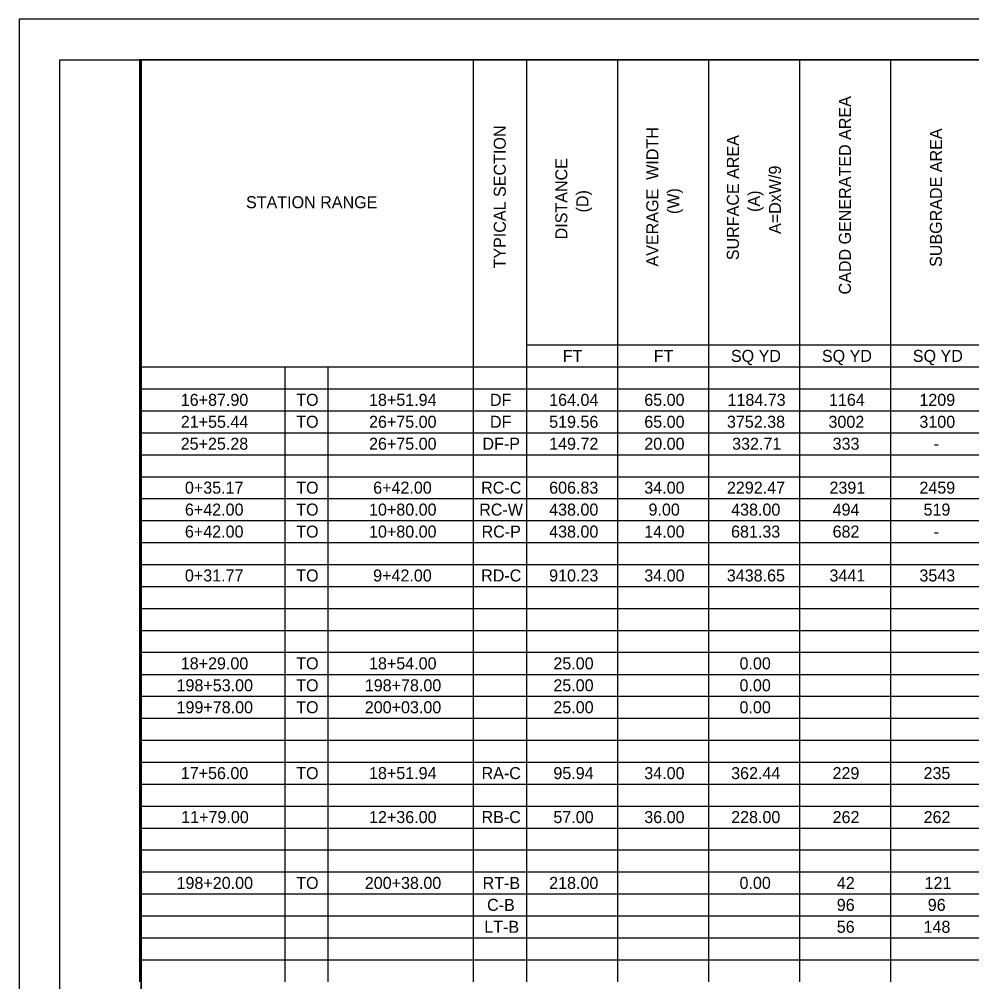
# Model space of a CAD drawing. Extents: x 0 to 34, y 0 to 22.
# Drawn here: x 0 to 11.72, y 10.15 to 22 of the extents above; entities that cross this region are included whole.
import ezdxf

# ---------------------------------------------------------------- set-up
doc = ezdxf.new("R2010")
doc.units = 0
for name, color, linetype in [('SH_Border', 7, 'Continuous'), ('SH_Cut_Line', 7, 'Continuous'), ('SH_Text', 7, 'Continuous')]:
    doc.layers.add(name, color=color, linetype=linetype)

msp = doc.modelspace()

# ---------------------------------------------------------------- linework, layer by layer
at = {"layer": 'SH_Border'}
for points in [[(0.5, 21.5), (1.5, 21.5), (1.5, 0.5), (0.5, 0.5)], [(1.5, 21.5), (33.5, 21.5), (33.5, 0.5), (1.5, 0.5)]]:
    msp.add_lwpolyline(points, close=True, dxfattribs=at)
at = {"layer": 'SH_Cut_Line'}
msp.add_lwpolyline([(0, 0), (34, 0), (34, 22), (0, 22)], close=True, dxfattribs=at)
at = {"layer": 'SH_Text'}
for p, q in [((1.479, 21.505), (6.242, 21.505)), ((1.479, 21.505), (1.479, 21.235)), ((5.585, 21.505), (5.585, 21.235)), ((6.242, 21.505), (7.362, 21.505)), ((6.242, 21.505), (6.242, 21.235)), ((7.362, 21.505), (8.482, 21.505)), ((7.362, 21.505), (7.362, 21.235)), ((8.482, 21.505), (10.722, 21.505)), ((8.482, 21.505), (8.482, 21.235)), ((9.602, 21.505), (9.602, 21.235)), ((10.722, 21.505), (11.841, 21.505)), ((10.722, 21.505), (10.722, 21.235)), ((1.479, 21.235), (1.479, 20.965)), ((5.585, 21.235), (5.585, 20.965)), ((6.242, 21.235), (6.242, 20.965)), ((7.362, 21.235), (7.362, 20.965)), ((8.482, 21.235), (8.482, 20.965)), ((9.602, 21.235), (9.602, 20.965)), ((10.722, 21.235), (10.722, 20.965)), ((1.479, 20.965), (1.479, 20.694)), ((5.585, 20.965), (5.585, 20.694)), ((6.242, 20.965), (6.242, 20.694)), ((7.362, 20.965), (7.362, 20.694)), ((8.482, 20.965), (8.482, 20.694)), ((9.602, 20.965), (9.602, 20.694)), ((10.722, 20.965), (10.722, 20.694)), ((1.479, 20.694), (1.479, 20.154)), ((5.585, 20.694), (5.585, 20.154)), ((6.242, 20.694), (6.242, 20.154)), ((7.362, 20.694), (7.362, 20.154)), ((8.482, 20.694), (8.482, 20.154)), ((9.602, 20.694), (9.602, 20.154)), ((10.722, 20.694), (10.722, 20.154)), ((1.479, 20.154), (1.479, 19.883)), ((5.585, 20.154), (5.585, 19.883)), ((6.242, 20.154), (6.242, 19.883)), ((7.362, 20.154), (7.362, 19.883)), ((8.482, 20.154), (8.482, 19.883)), ((9.602, 20.154), (9.602, 19.883)), ((10.722, 20.154), (10.722, 19.883)), ((1.479, 19.883), (1.479, 19.613)), ((5.585, 19.883), (5.585, 19.613)), ((6.242, 19.883), (6.242, 19.613)), ((7.362, 19.883), (7.362, 19.613)), ((8.482, 19.883), (8.482, 19.613)), ((9.602, 19.883), (9.602, 19.613)), ((10.722, 19.883), (10.722, 19.613)), ((1.479, 19.613), (1.479, 19.343)), ((5.585, 19.613), (5.585, 19.343)), ((6.242, 19.613), (6.242, 19.343)), ((7.362, 19.613), (7.362, 19.343)), ((8.482, 19.613), (8.482, 19.343)), ((9.602, 19.613), (9.602, 19.343)), ((10.722, 19.613), (10.722, 19.343)), ((1.479, 19.343), (1.479, 19.072)), ((5.585, 19.343), (5.585, 19.072)), ((6.242, 19.343), (6.242, 19.072)), ((7.362, 19.343), (7.362, 19.072)), ((8.482, 19.343), (8.482, 19.072)), ((9.602, 19.343), (9.602, 19.072)), ((10.722, 19.343), (10.722, 19.072)), ((1.479, 19.072), (1.479, 18.802)), ((5.585, 19.072), (5.585, 18.802)), ((6.242, 19.072), (6.242, 18.802)), ((7.362, 19.072), (7.362, 18.802)), ((8.482, 19.072), (8.482, 18.802)), ((9.602, 19.072), (9.602, 18.802)), ((10.722, 19.072), (10.722, 18.802)), ((1.479, 18.802), (1.479, 18.532)), ((5.585, 18.802), (5.585, 18.532)), ((6.242, 18.802), (6.242, 18.532)), ((7.362, 18.802), (7.362, 18.532)), ((8.482, 18.802), (8.482, 18.532)), ((9.602, 18.802), (9.602, 18.532)), ((10.722, 18.802), (10.722, 18.532)), ((1.479, 18.532), (1.479, 18.262)), ((5.585, 18.532), (5.585, 18.262)), ((6.242, 18.532), (6.242, 18.262)), ((7.362, 18.532), (7.362, 18.262)), ((8.482, 18.532), (8.482, 18.262)), ((9.602, 18.532), (9.602, 18.262)), ((10.722, 18.532), (10.722, 18.262)), ((1.479, 18.262), (1.479, 17.991)), ((5.585, 18.262), (5.585, 17.991)), ((6.242, 18.262), (6.242, 17.991)), ((7.362, 18.262), (7.362, 17.991)), ((8.482, 18.262), (8.482, 17.991)), ((9.602, 18.262), (9.602, 17.991)), ((10.722, 18.262), (10.722, 17.991)), ((1.479, 17.991), (1.479, 17.721)), ((5.585, 17.991), (5.585, 17.721)), ((6.242, 17.991), (7.362, 17.991)), ((6.242, 17.991), (6.242, 17.721)), ((7.362, 17.991), (8.482, 17.991)), ((7.362, 17.991), (7.362, 17.721)), ((8.482, 17.991), (10.722, 17.991)), ((8.482, 17.991), (8.482, 17.721)), ((9.602, 17.991), (9.602, 17.721)), ((10.722, 17.991), (11.841, 17.991)), ((10.722, 17.991), (10.722, 17.721)), ((1.479, 17.721), (6.242, 17.721)), ((1.479, 17.721), (1.479, 17.451)), ((3.268, 17.721), (3.268, 17.451)), ((3.796, 17.721), (3.796, 17.451)), ((5.585, 17.721), (5.585, 17.451)), ((6.242, 17.721), (7.362, 17.721)), ((6.242, 17.721), (6.242, 17.451)), ((7.362, 17.721), (8.482, 17.721)), ((7.362, 17.721), (7.362, 17.451)), ((8.482, 17.721), (10.722, 17.721)), ((8.482, 17.721), (8.482, 17.451)), ((9.602, 17.721), (9.602, 17.451)), ((10.722, 17.721), (11.841, 17.721)), ((10.722, 17.721), (10.722, 17.451)), ((1.479, 17.451), (6.242, 17.451)), ((1.479, 17.451), (1.479, 17.18)), ((3.268, 17.451), (3.268, 17.18)), ((3.796, 17.451), (3.796, 17.18)), ((5.585, 17.451), (5.585, 17.18)), ((6.242, 17.451), (7.362, 17.451)), ((6.242, 17.451), (6.242, 17.18)), ((7.362, 17.451), (8.482, 17.451)), ((7.362, 17.451), (7.362, 17.18)), ((8.482, 17.451), (10.722, 17.451)), ((8.482, 17.451), (8.482, 17.18)), ((9.602, 17.451), (9.602, 17.18)), ((10.722, 17.451), (11.841, 17.451)), ((10.722, 17.451), (10.722, 17.18)), ((1.479, 17.18), (6.242, 17.18)), ((1.479, 17.18), (1.479, 16.91)), ((3.268, 17.18), (3.268, 16.91)), ((3.796, 17.18), (3.796, 16.91)), ((5.585, 17.18), (5.585, 16.91)), ((6.242, 17.18), (7.362, 17.18)), ((6.242, 17.18), (6.242, 16.91)), ((7.362, 17.18), (8.482, 17.18)), ((7.362, 17.18), (7.362, 16.91)), ((8.482, 17.18), (10.722, 17.18)), ((8.482, 17.18), (8.482, 16.91)), ((9.602, 17.18), (9.602, 16.91)), ((10.722, 17.18), (11.841, 17.18)), ((10.722, 17.18), (10.722, 16.91)), ((1.479, 16.91), (6.242, 16.91)), ((1.479, 16.91), (1.479, 16.369)), ((3.268, 16.91), (3.268, 16.369)), ((3.796, 16.91), (3.796, 16.369)), ((5.585, 16.91), (5.585, 16.369)), ((6.242, 16.91), (7.362, 16.91)), ((6.242, 16.91), (6.242, 16.369)), ((7.362, 16.91), (8.482, 16.91)), ((7.362, 16.91), (7.362, 16.369)), ((8.482, 16.91), (10.722, 16.91)), ((8.482, 16.91), (8.482, 16.369)), ((9.602, 16.91), (9.602, 16.369)), ((10.722, 16.91), (11.841, 16.91)), ((10.722, 16.91), (10.722, 16.369)), ((1.479, 16.64), (6.242, 16.64)), ((6.242, 16.64), (7.362, 16.64)), ((7.362, 16.64), (8.482, 16.64)), ((8.482, 16.64), (10.722, 16.64)), ((10.722, 16.64), (11.841, 16.64)), ((1.479, 16.369), (6.242, 16.369)), ((1.479, 16.369), (1.479, 16.099)), ((3.268, 16.369), (3.268, 16.099)), ((3.796, 16.369), (3.796, 16.099)), ((5.585, 16.369), (5.585, 16.099)), ((6.242, 16.369), (7.362, 16.369)), ((6.242, 16.369), (6.242, 16.099)), ((7.362, 16.369), (8.482, 16.369)), ((7.362, 16.369), (7.362, 16.099)), ((8.482, 16.369), (10.722, 16.369)), ((8.482, 16.369), (8.482, 16.099)), ((9.602, 16.369), (9.602, 16.099)), ((10.722, 16.369), (11.841, 16.369)), ((10.722, 16.369), (10.722, 16.099)), ((1.479, 16.099), (6.242, 16.099)), ((1.479, 16.099), (1.479, 15.829)), ((3.268, 16.099), (3.268, 15.829)), ((3.796, 16.099), (3.796, 15.829)), ((5.585, 16.099), (5.585, 15.829)), ((6.242, 16.099), (7.362, 16.099)), ((6.242, 16.099), (6.242, 15.829)), ((7.362, 16.099), (8.482, 16.099)), ((7.362, 16.099), (7.362, 15.829)), ((8.482, 16.099), (10.722, 16.099)), ((8.482, 16.099), (8.482, 15.829)), ((9.602, 16.099), (9.602, 15.829)), ((10.722, 16.099), (11.841, 16.099)), ((10.722, 16.099), (10.722, 15.829)), ((1.479, 15.829), (6.242, 15.829)), ((1.479, 15.829), (1.479, 15.558)), ((3.268, 15.829), (3.268, 15.558)), ((3.796, 15.829), (3.796, 15.558)), ((5.585, 15.829), (5.585, 15.558)), ((6.242, 15.829), (7.362, 15.829)), ((6.242, 15.829), (6.242, 15.558)), ((7.362, 15.829), (8.482, 15.829)), ((7.362, 15.829), (7.362, 15.558)), ((8.482, 15.829), (10.722, 15.829)), ((8.482, 15.829), (8.482, 15.558)), ((9.602, 15.829), (9.602, 15.558)), ((10.722, 15.829), (11.841, 15.829)), ((10.722, 15.829), (10.722, 15.558)), ((1.479, 15.558), (6.242, 15.558)), ((1.479, 15.558), (1.479, 15.018)), ((3.268, 15.558), (3.268, 15.018)), ((3.796, 15.558), (3.796, 15.018)), ((5.585, 15.558), (5.585, 15.018)), ((6.242, 15.558), (7.362, 15.558)), ((6.242, 15.558), (6.242, 15.018)), ((7.362, 15.558), (8.482, 15.558)), ((7.362, 15.558), (7.362, 15.018)), ((8.482, 15.558), (10.722, 15.558)), ((8.482, 15.558), (8.482, 15.018)), ((9.602, 15.558), (9.602, 15.018)), ((10.722, 15.558), (11.841, 15.558)), ((10.722, 15.558), (10.722, 15.018)), ((1.479, 15.288), (6.242, 15.288)), ((6.242, 15.288), (7.362, 15.288)), ((7.362, 15.288), (8.482, 15.288)), ((8.482, 15.288), (10.722, 15.288)), ((10.722, 15.288), (11.841, 15.288)), ((1.479, 15.018), (6.242, 15.018)), ((1.479, 15.018), (1.479, 14.747)), ((3.268, 15.018), (3.268, 14.747)), ((3.796, 15.018), (3.796, 14.747)), ((5.585, 15.018), (5.585, 14.747)), ((6.242, 15.018), (7.362, 15.018)), ((6.242, 15.018), (6.242, 14.747)), ((7.362, 15.018), (8.482, 15.018)), ((7.362, 15.018), (7.362, 14.747)), ((8.482, 15.018), (10.722, 15.018)), ((8.482, 15.018), (8.482, 14.747)), ((9.602, 15.018), (9.602, 14.747)), ((10.722, 15.018), (11.841, 15.018)), ((10.722, 15.018), (10.722, 14.747)), ((1.479, 14.747), (6.242, 14.747)), ((1.479, 14.747), (1.479, 14.477)), ((3.268, 14.747), (3.268, 14.477)), ((3.796, 14.747), (3.796, 14.477)), ((5.585, 14.747), (5.585, 14.477)), ((6.242, 14.747), (7.362, 14.747)), ((6.242, 14.747), (6.242, 14.477)), ((7.362, 14.747), (8.482, 14.747)), ((7.362, 14.747), (7.362, 14.477)), ((8.482, 14.747), (10.722, 14.747)), ((8.482, 14.747), (8.482, 14.477)), ((9.602, 14.747), (9.602, 14.477)), ((10.722, 14.747), (11.841, 14.747)), ((10.722, 14.747), (10.722, 14.477)), ((1.479, 14.477), (6.242, 14.477)), ((1.479, 14.477), (1.479, 14.207)), ((3.268, 14.477), (3.268, 14.207)), ((3.796, 14.477), (3.796, 14.207)), ((5.585, 14.477), (5.585, 14.207)), ((6.242, 14.477), (7.362, 14.477)), ((6.242, 14.477), (6.242, 14.207)), ((7.362, 14.477), (8.482, 14.477)), ((7.362, 14.477), (7.362, 14.207)), ((8.482, 14.477), (10.722, 14.477)), ((8.482, 14.477), (8.482, 14.207)), ((9.602, 14.477), (9.602, 14.207)), ((10.722, 14.477), (11.841, 14.477)), ((10.722, 14.477), (10.722, 14.207)), ((1.479, 14.207), (6.242, 14.207)), ((1.479, 14.207), (1.479, 13.396)), ((3.268, 14.207), (3.268, 13.396)), ((3.796, 14.207), (3.796, 13.396)), ((5.585, 14.207), (5.585, 13.396)), ((6.242, 14.207), (7.362, 14.207)), ((6.242, 14.207), (6.242, 13.396)), ((7.362, 14.207), (8.482, 14.207)), ((7.362, 14.207), (7.362, 13.396)), ((8.482, 14.207), (10.722, 14.207)), ((8.482, 14.207), (8.482, 13.396)), ((9.602, 14.207), (9.602, 13.396)), ((10.722, 14.207), (11.841, 14.207)), ((10.722, 14.207), (10.722, 13.396)), ((1.479, 13.936), (6.242, 13.936)), ((6.242, 13.936), (7.362, 13.936)), ((7.362, 13.936), (8.482, 13.936)), ((8.482, 13.936), (10.722, 13.936)), ((10.722, 13.936), (11.841, 13.936)), ((1.479, 13.666), (6.242, 13.666)), ((6.242, 13.666), (7.362, 13.666)), ((7.362, 13.666), (8.482, 13.666)), ((8.482, 13.666), (10.722, 13.666)), ((10.722, 13.666), (11.841, 13.666)), ((1.479, 13.396), (6.242, 13.396)), ((1.479, 13.396), (1.479, 13.125)), ((3.268, 13.396), (3.268, 13.125)), ((3.796, 13.396), (3.796, 13.125)), ((5.585, 13.396), (5.585, 13.125)), ((6.242, 13.396), (7.362, 13.396)), ((6.242, 13.396), (6.242, 13.125)), ((7.362, 13.396), (8.482, 13.396)), ((7.362, 13.396), (7.362, 13.125)), ((8.482, 13.396), (10.722, 13.396)), ((8.482, 13.396), (8.482, 13.125)), ((9.602, 13.396), (9.602, 13.125)), ((10.722, 13.396), (11.841, 13.396)), ((10.722, 13.396), (10.722, 13.125)), ((1.479, 13.125), (6.242, 13.125)), ((1.479, 13.125), (1.479, 12.044)), ((3.268, 13.125), (3.268, 12.044)), ((3.796, 13.125), (3.796, 12.044)), ((5.585, 13.125), (5.585, 12.044)), ((6.242, 13.125), (7.362, 13.125)), ((6.242, 13.125), (6.242, 12.044)), ((7.362, 13.125), (8.482, 13.125)), ((7.362, 13.125), (7.362, 12.044)), ((8.482, 13.125), (10.722, 13.125)), ((8.482, 13.125), (8.482, 12.044)), ((9.602, 13.125), (9.602, 12.044)), ((10.722, 13.125), (11.841, 13.125)), ((10.722, 13.125), (10.722, 12.044)), ((1.479, 12.855), (6.242, 12.855)), ((6.242, 12.855), (7.362, 12.855)), ((7.362, 12.855), (8.482, 12.855)), ((8.482, 12.855), (10.722, 12.855)), ((10.722, 12.855), (11.841, 12.855)), ((1.479, 12.585), (6.242, 12.585)), ((6.242, 12.585), (7.362, 12.585)), ((7.362, 12.585), (8.482, 12.585)), ((8.482, 12.585), (10.722, 12.585)), ((10.722, 12.585), (11.841, 12.585)), ((1.479, 12.314), (6.242, 12.314)), ((6.242, 12.314), (7.362, 12.314)), ((7.362, 12.314), (8.482, 12.314)), ((8.482, 12.314), (10.722, 12.314)), ((10.722, 12.314), (11.841, 12.314)), ((1.479, 12.044), (6.242, 12.044)), ((1.479, 12.044), (1.479, 11.774)), ((3.268, 12.044), (3.268, 11.774)), ((3.796, 12.044), (3.796, 11.774)), ((5.585, 12.044), (5.585, 11.774)), ((6.242, 12.044), (7.362, 12.044)), ((6.242, 12.044), (6.242, 11.774)), ((7.362, 12.044), (8.482, 12.044)), ((7.362, 12.044), (7.362, 11.774)), ((8.482, 12.044), (10.722, 12.044)), ((8.482, 12.044), (8.482, 11.774)), ((9.602, 12.044), (9.602, 11.774)), ((10.722, 12.044), (11.841, 12.044)), ((10.722, 12.044), (10.722, 11.774)), ((1.479, 11.774), (6.242, 11.774)), ((1.479, 11.774), (1.479, 10.692)), ((3.268, 11.774), (3.268, 10.692)), ((3.796, 11.774), (3.796, 10.692)), ((5.585, 11.774), (5.585, 10.692)), ((6.242, 11.774), (7.362, 11.774)), ((6.242, 11.774), (6.242, 10.692)), ((7.362, 11.774), (8.482, 11.774)), ((7.362, 11.774), (7.362, 10.692)), ((8.482, 11.774), (10.722, 11.774)), ((8.482, 11.774), (8.482, 10.692)), ((9.602, 11.774), (9.602, 10.692)), ((10.722, 11.774), (11.841, 11.774)), ((10.722, 11.774), (10.722, 10.692)), ((1.479, 11.503), (6.242, 11.503)), ((6.242, 11.503), (7.362, 11.503)), ((7.362, 11.503), (8.482, 11.503)), ((8.482, 11.503), (10.722, 11.503)), ((10.722, 11.503), (11.841, 11.503)), ((1.479, 11.233), (6.242, 11.233)), ((6.242, 11.233), (7.362, 11.233)), ((7.362, 11.233), (8.482, 11.233)), ((8.482, 11.233), (10.722, 11.233)), ((10.722, 11.233), (11.841, 11.233)), ((1.479, 10.963), (6.242, 10.963)), ((6.242, 10.963), (7.362, 10.963)), ((7.362, 10.963), (8.482, 10.963)), ((8.482, 10.963), (10.722, 10.963)), ((10.722, 10.963), (11.841, 10.963)), ((1.479, 10.692), (6.242, 10.692)), ((1.479, 10.692), (1.479, 10.152)), ((3.268, 10.692), (3.268, 10.152)), ((3.796, 10.692), (3.796, 10.152)), ((5.585, 10.692), (5.585, 10.152)), ((6.242, 10.692), (7.362, 10.692)), ((6.242, 10.692), (6.242, 10.152)), ((7.362, 10.692), (8.482, 10.692)), ((7.362, 10.692), (7.362, 10.152)), ((8.482, 10.692), (10.722, 10.692)), ((8.482, 10.692), (8.482, 10.152)), ((9.602, 10.692), (9.602, 10.152)), ((10.722, 10.692), (11.841, 10.692)), ((10.722, 10.692), (10.722, 10.152)), ((1.479, 10.422), (6.242, 10.422)), ((6.242, 10.422), (7.362, 10.422)), ((7.362, 10.422), (8.482, 10.422)), ((8.482, 10.422), (10.722, 10.422)), ((10.722, 10.422), (11.841, 10.422))]:
    msp.add_line(p, q, dxfattribs=at)

# ---------------------------------------------------------------- texts
for s, height, p in [('CADD GENERATED AREA', 0.14804, (10.236, 18.612)), ('TYPICAL SECTION', 0.14804, (5.988, 18.932)), ('AVERAGE  WIDTH', 0.14804, (7.866, 18.956)), ('SUBGRADE AREA', 0.14804, (11.356, 18.951)), ('SURFACE AREA', 0.14804, (8.857, 19.034)), ('DISTANCE', 0.148, (6.746, 19.29)), ('A=DxW/9', 0.148, (9.375, 19.357)), ('(W)', 0.148, (8.125, 19.602)), ('(D)', 0.148, (7.005, 19.622)), ('(A)', 0.148, (9.116, 19.628))]:
    msp.add_text(s, height=height, rotation=90, dxfattribs=at).set_placement(p)
for s, height, p in [('STATION RANGE', 0.14804, (2.791, 19.674)), ('FT', 0.148, (6.69, 17.782)), ('FT', 0.148, (7.81, 17.782)), ('SQ YD', 0.148, (8.759, 17.782)), ('SQ YD', 0.148, (9.879, 17.782)), ('SQ YD', 0.148, (10.998, 17.782)), ('16+87.90', 0.148, (1.988, 17.241)), ('TO', 0.148, (3.409, 17.241)), ('18+51.94', 0.148, (4.305, 17.241)), ('DF', 0.148, (5.794, 17.241)), ('164.04', 0.148, (6.522, 17.241)), ('65.00', 0.148, (7.693, 17.241)), ('1184.73', 0.148, (8.717, 17.241)), ('1164', 0.148, (9.966, 17.241)), ('1209', 0.148, (11.079, 17.241)), ('21+55.44', 0.148, (1.988, 16.971)), ('TO', 0.148, (3.409, 16.971)), ('26+75.00', 0.148, (4.305, 16.971)), ('DF', 0.148, (5.794, 16.971)), ('519.56', 0.148, (6.522, 16.971)), ('65.00', 0.148, (7.693, 16.971)), ('3752.38', 0.148, (8.71, 16.971)), ('3002', 0.148, (9.96, 16.971)), ('3100', 0.148, (11.079, 16.971)), ('25+25.28', 0.148, (1.987, 16.701)), ('26+75.00', 0.148, (4.305, 16.701)), ('DF-P', 0.148, (5.701, 16.701)), ('149.72', 0.148, (6.522, 16.701)), ('20.00', 0.148, (7.693, 16.701)), ('332.71', 0.148, (8.774, 16.701)), ('333', 0.148, (10.011, 16.701)), ('-', 0.148, (11.253, 16.701)), ('0+35.17', 0.148, (2.039, 16.16)), ('TO', 0.148, (3.409, 16.16)), ('6+42.00', 0.148, (4.356, 16.16)), ('RC-C', 0.148, (5.685, 16.16)), ('606.83', 0.148, (6.522, 16.16)), ('34.00', 0.148, (7.693, 16.16)), ('2292.47', 0.148, (8.71, 16.16)), ('2391', 0.148, (9.972, 16.16)), ('2459', 0.148, (11.079, 16.16)), ('6+42.00', 0.148, (2.039, 15.89)), ('TO', 0.148, (3.409, 15.89)), ('10+80.00', 0.148, (4.305, 15.89)), ('RC-W', 0.148, (5.661, 15.89)), ('438.00', 0.148, (6.522, 15.89)), ('9.00', 0.148, (7.745, 15.89)), ('438.00', 0.148, (8.762, 15.89)), ('494', 0.148, (10.011, 15.89)), ('519', 0.148, (11.13, 15.89)), ('6+42.00', 0.148, (2.039, 15.619)), ('TO', 0.148, (3.409, 15.619)), ('10+80.00', 0.148, (4.305, 15.619)), ('RC-P', 0.148, (5.69, 15.619)), ('438.00', 0.148, (6.522, 15.619)), ('14.00', 0.148, (7.693, 15.619)), ('681.33', 0.148, (8.761, 15.619)), ('682', 0.148, (10.011, 15.619)), ('-', 0.148, (11.253, 15.619)), ('0+31.77', 0.148, (2.039, 15.079)), ('TO', 0.148, (3.409, 15.079)), ('9+42.00', 0.148, (4.356, 15.079)), ('RD-C', 0.148, (5.685, 15.079)), ('910.23', 0.148, (6.522, 15.079)), ('34.00', 0.148, (7.693, 15.079)), ('3438.65', 0.148, (8.709, 15.079)), ('3441', 0.148, (9.972, 15.079)), ('3543', 0.148, (11.079, 15.079)), ('18+29.00', 0.148, (1.988, 13.997)), ('TO', 0.148, (3.409, 13.997)), ('18+54.00', 0.148, (4.305, 13.997)), ('25.00', 0.148, (6.574, 13.997)), ('0.00', 0.148, (8.865, 13.997)), ('198+53.00', 0.148, (1.936, 13.727)), ('TO', 0.148, (3.409, 13.727)), ('198+78.00', 0.148, (4.253, 13.727)), ('25.00', 0.148, (6.574, 13.727)), ('0.00', 0.148, (8.865, 13.727)), ('199+78.00', 0.148, (1.936, 13.457)), ('TO', 0.148, (3.409, 13.457)), ('200+03.00', 0.148, (4.253, 13.457)), ('25.00', 0.148, (6.574, 13.457)), ('0.00', 0.148, (8.865, 13.457)), ('17+56.00', 0.148, (1.988, 12.646)), ('TO', 0.148, (3.409, 12.646)), ('18+51.94', 0.148, (4.305, 12.646)), ('RA-C', 0.148, (5.69, 12.646)), ('95.94', 0.148, (6.574, 12.646)), ('34.00', 0.148, (7.693, 12.646)), ('362.44', 0.148, (8.762, 12.646)), ('229', 0.148, (10.01, 12.646)), ('235', 0.148, (11.13, 12.646)), ('11+79.00', 0.148, (1.994, 12.105)), ('12+36.00', 0.148, (4.305, 12.105)), ('RB-C', 0.148, (5.69, 12.105)), ('57.00', 0.148, (6.574, 12.105)), ('36.00', 0.148, (7.693, 12.105)), ('228.00', 0.148, (8.762, 12.105)), ('262', 0.148, (10.011, 12.105)), ('262', 0.148, (11.131, 12.105)), ('198+20.00', 0.148, (1.936, 11.294)), ('TO', 0.148, (3.409, 11.294)), ('200+38.00', 0.148, (4.253, 11.294)), ('RT-B', 0.148, (5.703, 11.294)), ('218.00', 0.148, (6.522, 11.294)), ('0.00', 0.148, (8.865, 11.294)), ('42', 0.148, (10.063, 11.294)), ('121', 0.148, (11.143, 11.294)), ('C-B', 0.148, (5.758, 11.024)), ('96', 0.148, (10.062, 11.024)), ('96', 0.148, (11.182, 11.024)), ('LT-B', 0.148, (5.724, 10.754)), ('56', 0.148, (10.062, 10.754)), ('148', 0.148, (11.13, 10.754))]:
    msp.add_text(s, height=height, dxfattribs=at).set_placement(p)

doc.saveas('drawing.dxf')
